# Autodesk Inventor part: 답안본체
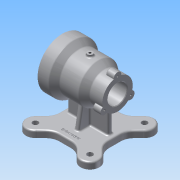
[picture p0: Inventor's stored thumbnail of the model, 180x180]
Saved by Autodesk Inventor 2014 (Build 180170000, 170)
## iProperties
Created: 2017-03
Part Number: 답안본체
Material: 알루미늄 6061
Document SubType Name: Modeling
Designer: NET
Density: 2.71 g/cm^3
Appearance: 알루미늄 - 평지
Mass: 1009.74 g
Surface Area: 851.342 cm^2
Volume: 372.6 cm^3
Author: NET
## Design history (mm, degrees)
sketch "스케치2"
  geometry: L1 (0, 70)-(0, -70); L2 (-70, 0)-(70, 0); L3 (-49.497, -49.497)-(49.497, 49.497); L4 (49.497, -49.497)-(-49.497, 49.497); L5 (-52.322, 28.281)-(-61.518, 37.477); L6 (-28.281, 52.322)-(-37.477, 61.518); L7 (-61.518, -37.477)-(-52.322, -28.281); L8 (-37.477, -61.518)-(-28.281, -52.322); L9 (0, 0)-(45, 0); L10 (0, 0)-(0, -45); L11 (-10.603, 45)-(10.603, 45); L12 (45, 10.603)-(45, -10.603); L13 (10.603, -45)-(-10.603, -45); L14 (-45, -10.603)-(-45, 10.603); L15 (-45, 45)-(45, -45); L16 (45, 45)-(-45, -45); L17 (28.281, 52.322)-(37.477, 61.518); L18 (28.281, -52.322)-(35.995, -60.036); L19 (61.518, -37.477)-(52.322, -28.281); L20 (52.322, 28.281)-(61.518, 37.477); A1 r 17 centre (-49.497, 49.497) between (-36.106, 59.97) and (-59.97, 36.106); A2 r 17 centre (-49.497, -49.497) between (-59.97, -36.106) and (-36.106, -59.97); A3 r 17 centre (49.497, -49.497) between (36.106, -59.97) and (59.97, -36.106); A4 r 17 centre (49.497, 49.497) between (59.97, 36.106) and (36.106, 59.97); A5 r 25 centre (-70, 10.603) between (-45, 10.603) and (-52.322, 28.281); A6 r 25 centre (-70, -10.603) between (-52.322, -28.281) and (-45, -10.603); A7 r 25 centre (-10.603, 70) between (-28.281, 52.322) and (-10.603, 45); A8 r 25 centre (-10.603, -70) between (-10.603, -45) and (-28.281, -52.322); A9 r 25 centre (10.603, 70) between (10.603, 45) and (28.281, 52.322); A10 r 25 centre (10.603, -70) between (28.281, -52.322) and (10.603, -45); A11 r 25 centre (70, -10.603) between (45, -10.603) and (52.322, -28.281); A12 r 25 centre (70, 10.603) between (52.322, 28.281) and (45, 10.603); A13 r 70 centre (0, 0) between (-35.995, 60.036) and (-60.036, 35.995); A14 r 70 centre (0, 0) between (60.036, 35.995) and (35.995, 60.036); A15 r 70 centre (0, 0) between (-60.036, -35.995) and (-35.995, -60.036); A16 r 70 centre (0, 0) between (35.995, -60.036) and (60.036, -35.995); 1 further point
  constraints: 44 point on circle, 40 end point, 18 point on line, 16 centre point, 16 tangent, 10 parallel, 5 coincident, 4 equal radius, 4 midpoint, 2 perpendicular, 1 horizontal, 1 vertical
  dimensions: "d25" = 140 distance of L1.start L1.end; "d26" = 140 distance of L2.start L2.end; "d27" = 45 deg angle of L1 L3; "d28" = 45 deg angle of L1 L4; "d29" = 34 diameter of A1; "d30" = 34 diameter of A2; "d31" = 34 diameter of A3; "d32" = 34 diameter of A4; "d33" = 17 distance between parallel lines of L4 L5; "d34" = 17 distance between parallel lines of L6 L4; "d35" = 17 distance between parallel lines of L7 L3; "d36" = 17 distance between parallel lines of L8 L3; "d37" = 45 distance of L9.start L9.end; "d38" = 45 distance of L9.start L10.end; "d39" = 90 distance of L15.start L16.start; "d40" = 25 radius of A5; "d41" = 17 distance between parallel lines of L19 L4; "d42" = 17 distance between parallel lines of L18 L15; "d43" = 17 distance between parallel lines of L17 L3; "d44" = 25 radius of A9; "d45" = 25 radius of A10; "d46" = 17 distance between parallel lines of L20 L3; "d47" = 25 radius of A12; "d48" = 45 distance between parallel lines of L13 L2; "d49" = 98.99495 horizontal distance of A4.centre A2.centre; "d50" = 98.99495 horizontal distance of A1.centre A3.centre; "d51" = 98.99495 distance of A3.centre A4.centre; "d52" = 70 radius of A16; "d53" = 45 distance between parallel lines of L14 L1
extrude "돌출1" new body sketch "스케치2" distance "d54" = 12; taper "d55" = 0 deg
node "작업 평면1"
sketch "스케치3"
  geometry: L1 (-55.894, 0)-(-55.894, 12) reference; L2 (77.101, 0)-(77.101, 12) reference; L3 (10.603, 0)-(10.603, 82); L4 (10.603, 82)-(-39.397, 82); L5 (-39.397, 82)-(-39.397, 127); L6 (-39.397, 127)-(-19.397, 127); L7 (10.603, 82)-(60.603, 82); L8 (60.603, 82)-(60.603, 109.5); L9 (-39.397, 82)-(-8.397, 82); L10 (-8.397, 118)-(-19.397, 127); L11 (60.603, 109.5)-(37.603, 109.5); L12 (-39.397, 82)-(25.603, 82); L13 (25.603, 118)-(-8.397, 118); L14 (25.603, 118)-(37.603, 109.5); L15 (-39.397, 82)-(-16.397, 82); L16 (-16.397, 82)-(-16.397, 114); L17 (-19.397, 117)-(-39.397, 117); L18 (-8.397, 117)-(-8.397, 118); L19 (60.603, 82)-(30.603, 82); L20 (30.603, 82)-(30.603, 99.5); L21 (33.603, 99.5)-(60.603, 99.5); L22 (-16.397, 82)-(-16.397, 105); L23 (-13.397, 108)-(27.603, 108); L24 (30.603, 105)-(30.603, 82); A1 r 3 centre (-19.397, 114) between (-16.397, 114) and (-19.397, 117); A2 r 3 centre (-13.397, 105) between (-13.397, 108) and (-16.397, 105); A3 r 3 centre (27.603, 105) between (30.603, 105) and (27.603, 108); A4 r 3 centre (33.603, 102.5) between (30.603, 102.5) and (33.603, 99.5); 2 further points
  constraints: 44 end point, 15 point on line, 10 perpendicular, 8 point on circle, 8 tangent, 5 parallel, 4 centre point, 2 equal radius
  dimensions: "d56" = 82 distance of L3.start L3.end; "d57" = 50 distance of L3.end L4.end; "d58" = 45 distance of L4.end L5.end; "d59" = 20 distance of L5.end L6.end; "d60" = 50 distance of L3.end L7.end; "d61" = 27.5 distance of L7.end L8.end; "d62" = 31 distance of L4.end L9.end; "d63" = 36 distance of L9.end L10.start; "d64" = 23 distance of L8.end L11.end; "d65" = 65 distance of L4.end L12.end; "d66" = 23 distance of L4.end L15.end; "d67" = 35 distance of L15.end point (-16.397, 117); "d68" = 36 distance between parallel lines of L12 L13; "d69" = 12 horizontal distance of L13.start L11.end; "d70" = 30 distance of L19.end L7.end; "d71" = 17.5 distance of L19.end L20.end; "d72" = 26 distance of L15.end point (-16.397, 108); "d73" = 3 radius of A1; "d74" = 3 radius of A4
revolve "회전1" sketch "스케치3" stored, may be unused: angle "d75" = 90 deg
sketch "스케치4" dims "d76" = 80
  geometry: C1 r 45 at (0, 0) reference; C2 r 2.5 at (40, 0); C3 r 2.5 at (20, 34.641); C4 r 2.5 at (-20, 34.641); C5 r 2.5 at (-40, 0); C6 r 2.5 at (-20, -34.641); C7 r 2.5 at (20, -34.641); 2 further points
  constraints: 6 centre point, 1 coincident, 1 horizontal alignment, 15 other
  dimensions: "d77" = 5 diameter of C2; "d80" = 360 deg dimension on point (0, 0) C2.centre (derived); "d82" = 34.64102 vertical distance of C2.centre C3.centre
hole "구멍1" sketch "스케치4" at (-40, 0), (-20, -34.641), (20, -34.641), (40, 0), (20, 34.641), (-20, 34.641) diameter "d83" = 3.242; stored, may be unused: countersink angle "d87" = 90 deg, drill point angle "d89" = 118 deg; dims "d84" = 9, "d85" = 4, "d86" = 2, "d88" = 11
node "작업 평면3"
  node "작업 평면2"
sketch "스케치5"
  geometry: C1 r 5 at (0, 0); 1 further point
  constraints: 1 centre point, 1 coincident
  dimensions: "d92" = 10 diameter of C1
extrude "돌출2" join sketch "스케치5" stored distance "d93" = 12; taper "d94" = 0 deg
sketch "스케치6"
  geometry: C1 r 5 at (0, 0) reference; C2 r 2.5 at (0, 0)
  constraints: 1 centre point, 1 coincident
  dimensions: "d95" = 5 diameter of C2
hole "구멍2" sketch "스케치6" at (0, 0) diameter "d96" = 4.134; stored, may be unused: countersink angle "d100" = 90 deg, drill point angle "d102" = 118 deg; dims "d97" = 9, "d98" = 4, "d99" = 2, "d101" = 11
sketch "스케치7"
  geometry: C1 r 7 at (-27.5, 0); C2 r 7 at (13.75, -23.816); C3 r 7 at (13.75, 23.816); 2 further points
  constraints: 3 centre point, 1 horizontal alignment, 8 other
  dimensions: "d103" = 14 diameter of C1; "d106" = 360 deg dimension on point (0, 0) C1.centre (derived); "d108" = 23.8157 vertical distance of C1.centre C2.centre
extrude "돌출3" join sketch "스케치7" distance "d109" = 15; taper "d110" = 0 deg
sketch "스케치8"
  geometry: C1 r 2.5 at (0, 0); C2 r 2.5 at (41.25, 23.816); C3 r 2.5 at (41.25, -23.816); A1 r 7 centre (0, 0) between (0.891, 6.943) and (0.891, -6.943) reference; A2 r 7 centre (41.25, -23.816) between (34.792, -26.516) and (46.817, -19.573) reference; A3 r 7 centre (41.25, 23.816) between (46.817, 19.573) and (34.792, 26.516) reference; 1 further point
  constraints: 3 centre point, 3 coincident
  dimensions: "d111" = 5 diameter of C1; "d112" = 5 diameter of C2; "d113" = 5 diameter of C3
hole "구멍3" sketch "스케치8" at (0, 0), (41.25, -23.816), (41.25, 23.816) diameter "d114" = 3.242; stored, may be unused: countersink angle "d118" = 90 deg, drill point angle "d120" = 118 deg; dims "d115" = 9, "d116" = 4, "d117" = 2, "d119" = 11
sketch "스케치9"
  geometry: L1 (4, 4)-(37, 4); L2 (4, -4)-(37, -4); L3 (4, -4)-(4, -25); L4 (-4, -4)-(-4, -25); L5 (-4, 4)-(-37, 4); L6 (-4, 4)-(-4, 25); L7 (4, 4)-(4, 25); L8 (-4, -4)-(-37, -4); L9 (-37, 4)-(-37, -4); L10 (-4, 25)-(4, 25); L11 (-4, -25)-(4, -25); L12 (37, 4)-(37, -4); A1 r 70 centre (0, 0) between (59.97, -36.106) and (60.036, -35.995) reference; A2 r 70 centre (0, 0) between (35.995, -60.036) and (36.106, -59.97) reference
  constraints: 24 end point, 3 perpendicular, 2 horizontal, 2 vertical, 1 parallel
  dimensions: "d133" = 8 distance between parallel lines of L7 L6; "d134" = 8 distance between parallel lines of L2 L1; "d135" = 8 distance between parallel lines of L3 L4; "d136" = 8 distance between parallel lines of L5 L8; "d137" = 25 distance from line of A2.centre L10; "d138" = 37 distance from line of L12 A1.centre; "d139" = 37 distance from line of L9 A2.centre; "d140" = 4 distance from line of A1.centre L4; "d141" = 25 distance from line of L11 A1.centre; "d142" = 4 distance from line of A1.centre L1; "d143" = 4 distance from line of A1.centre L7; "d144" = 4 distance from line of A2.centre L8
extrude "돌출4" join sketch "스케치9" stored distance "d145" = 15; taper "d146" = 0 deg
feature "면 기울기1" dims angle "d147" = 10 deg
feature "면 기울기2" dims angle "d148" = 10 deg
sketch "스케치10"
  geometry: C1 r 5 at (-49.497, 49.497); C2 r 5 at (49.497, 49.497); C3 r 5 at (-49.497, -49.497); C4 r 5 at (49.497, -49.497); A1 r 17 centre (49.497, -49.497) between (36.106, -59.97) and (59.97, -36.106) reference; A2 r 17 centre (49.497, 49.497) between (59.97, 36.106) and (36.106, 59.97) reference; A3 r 17 centre (-49.497, 49.497) between (-36.106, 59.97) and (-59.97, 36.106) reference; A4 r 17 centre (-49.497, -49.497) between (-59.97, -36.106) and (-36.106, -59.97) reference
  constraints: 4 centre point, 4 coincident
  dimensions: "d149" = 10 diameter of C1; "d150" = 10 diameter of C2; "d151" = 10 diameter of C3; "d152" = 10 diameter of C4
extrude "돌출5" cut sketch "스케치10" stored distance "d153" = 15; taper "d154" = 0 deg
fillet "모깎기1" dims "d155" = 3
fillet "모깎기2" dims "d156" = 3
fillet "모깎기3" dims "d157" = 3
chamfer "모따기1" distance "d159" = 1; stored, may be unused: second distance "d160" = 2, angle "d161" = 45 deg
chamfer "모따기2" distance "d162" = 1; stored, may be unused: second distance "d163" = 2, angle "d164" = 45 deg
fillet "모깎기5" dims "d165" = 3
fillet "모깎기6" dims "d166" = 3
fillet "모깎기7" dims "d167" = 1
fillet "모깎기8" dims "d168" = 3
fillet "모깎기9" dims "d169" = 3
sketch "스케치11"
  geometry: L1 (52.322, 28.281)-(60.036, 35.995) reference; L2 (45, -10.603)-(45, 10.603) reference; L3 (60.036, -35.995)-(52.322, -28.281) reference; L4 (28.281, -52.322)-(35.995, -60.036) reference; L5 (-10.603, -45)-(10.603, -45) reference; L6 (-35.995, -60.036)-(-28.281, -52.322) reference; L7 (-52.322, -28.281)-(-60.036, -35.995) reference; L8 (-45, 10.603)-(-45, -10.603) reference; L9 (-60.036, 35.995)-(-52.322, 28.281) reference; L10 (-28.281, 52.322)-(-35.995, 60.036) reference; L11 (10.603, 45)-(-10.603, 45) reference; L12 (35.995, 60.036)-(28.281, 52.322) reference; L13 (45, 0)-(0, 0); L14 (0, 0)-(0, -35); C1 r 5 at (-49.497, -49.497) reference; C2 r 5 at (-49.497, 49.497) reference; C3 r 5 at (49.497, 49.497) reference; C4 r 5 at (49.497, -49.497) reference; A1 r 17 centre (49.497, 49.497) between (59.97, 36.106) and (36.106, 59.97) reference; A2 r 70 centre (0, 0) between (60.036, 35.995) and (59.97, 36.106) reference; A3 r 25 centre (70, 10.603) between (52.322, 28.281) and (45, 10.603) reference; A4 r 25 centre (70, -10.603) between (45, -10.603) and (52.322, -28.281) reference; A5 r 70 centre (0, 0) between (59.97, -36.106) and (60.036, -35.995) reference; A6 r 17 centre (49.497, -49.497) between (36.106, -59.97) and (59.97, -36.106) reference; A7 r 70 centre (0, 0) between (35.995, -60.036) and (36.106, -59.97) reference; A8 r 25 centre (10.603, -70) between (28.281, -52.322) and (10.603, -45) reference; A9 r 25 centre (-10.603, -70) between (-10.603, -45) and (-28.281, -52.322) reference; A10 r 70 centre (0, 0) between (-36.106, -59.97) and (-35.995, -60.036) reference; A11 r 17 centre (-49.497, -49.497) between (-59.97, -36.106) and (-36.106, -59.97) reference; A12 r 70 centre (0, 0) between (-60.036, -35.995) and (-59.97, -36.106) reference; A13 r 25 centre (-70, -10.603) between (-52.322, -28.281) and (-45, -10.603) reference; A14 r 25 centre (-70, 10.603) between (-45, 10.603) and (-52.322, 28.281) reference; A15 r 70 centre (0, 0) between (-59.97, 36.106) and (-60.036, 35.995) reference; A16 r 17 centre (-49.497, 49.497) between (-36.106, 59.97) and (-59.97, 36.106) reference; A17 r 70 centre (0, 0) between (-35.995, 60.036) and (-36.106, 59.97) reference; A18 r 25 centre (-10.603, 70) between (-28.281, 52.322) and (-10.603, 45) reference; A19 r 25 centre (10.603, 70) between (10.603, 45) and (28.281, 52.322) reference; A20 r 70 centre (0, 0) between (36.106, 59.97) and (35.995, 60.036) reference; 1 further point
  constraints: 4 end point, 1 coincident, 1 midpoint, 1 parallel, 1 perpendicular, 1 other
  dimensions: "d170" = 45 distance of L13.start L13.end (derived); "d171" = 35 distance of L13.end L14.end
feature "엠보싱1" sketch "스케치11" dims "d40" = 25, "d172" = 0.5, "d173" = 0
sketch "스케치13"
  geometry: C1 r 2.067 at (0, 0) reference; C2 r 5 at (0, 0) reference; C3 r 2.5 at (0, 0)
  constraints: 1 centre point, 1 coincident
  dimensions: "d182" = 5 diameter of C3
extrude "돌출6" join sketch "스케치13" stored distance "d183" = 10; taper "d184" = 0 deg
sketch "스케치14"
  geometry: C1 r 5 at (0, 0) reference; C2 r 2.5 at (0, 0)
  constraints: 1 centre point, 1 coincident
  dimensions: "d185" = 5 diameter of C2
hole "구멍5" sketch "스케치14" at (0, 0) diameter "d186" = 4.134; stored, may be unused: countersink angle "d190" = 90 deg, drill point angle "d192" = 118 deg; dims "d187" = 6, "d188" = 4, "d189" = 2, "d191" = 8
node "솔리드1"
node "투영된 루프1"
other parameters: "d90" = -82
